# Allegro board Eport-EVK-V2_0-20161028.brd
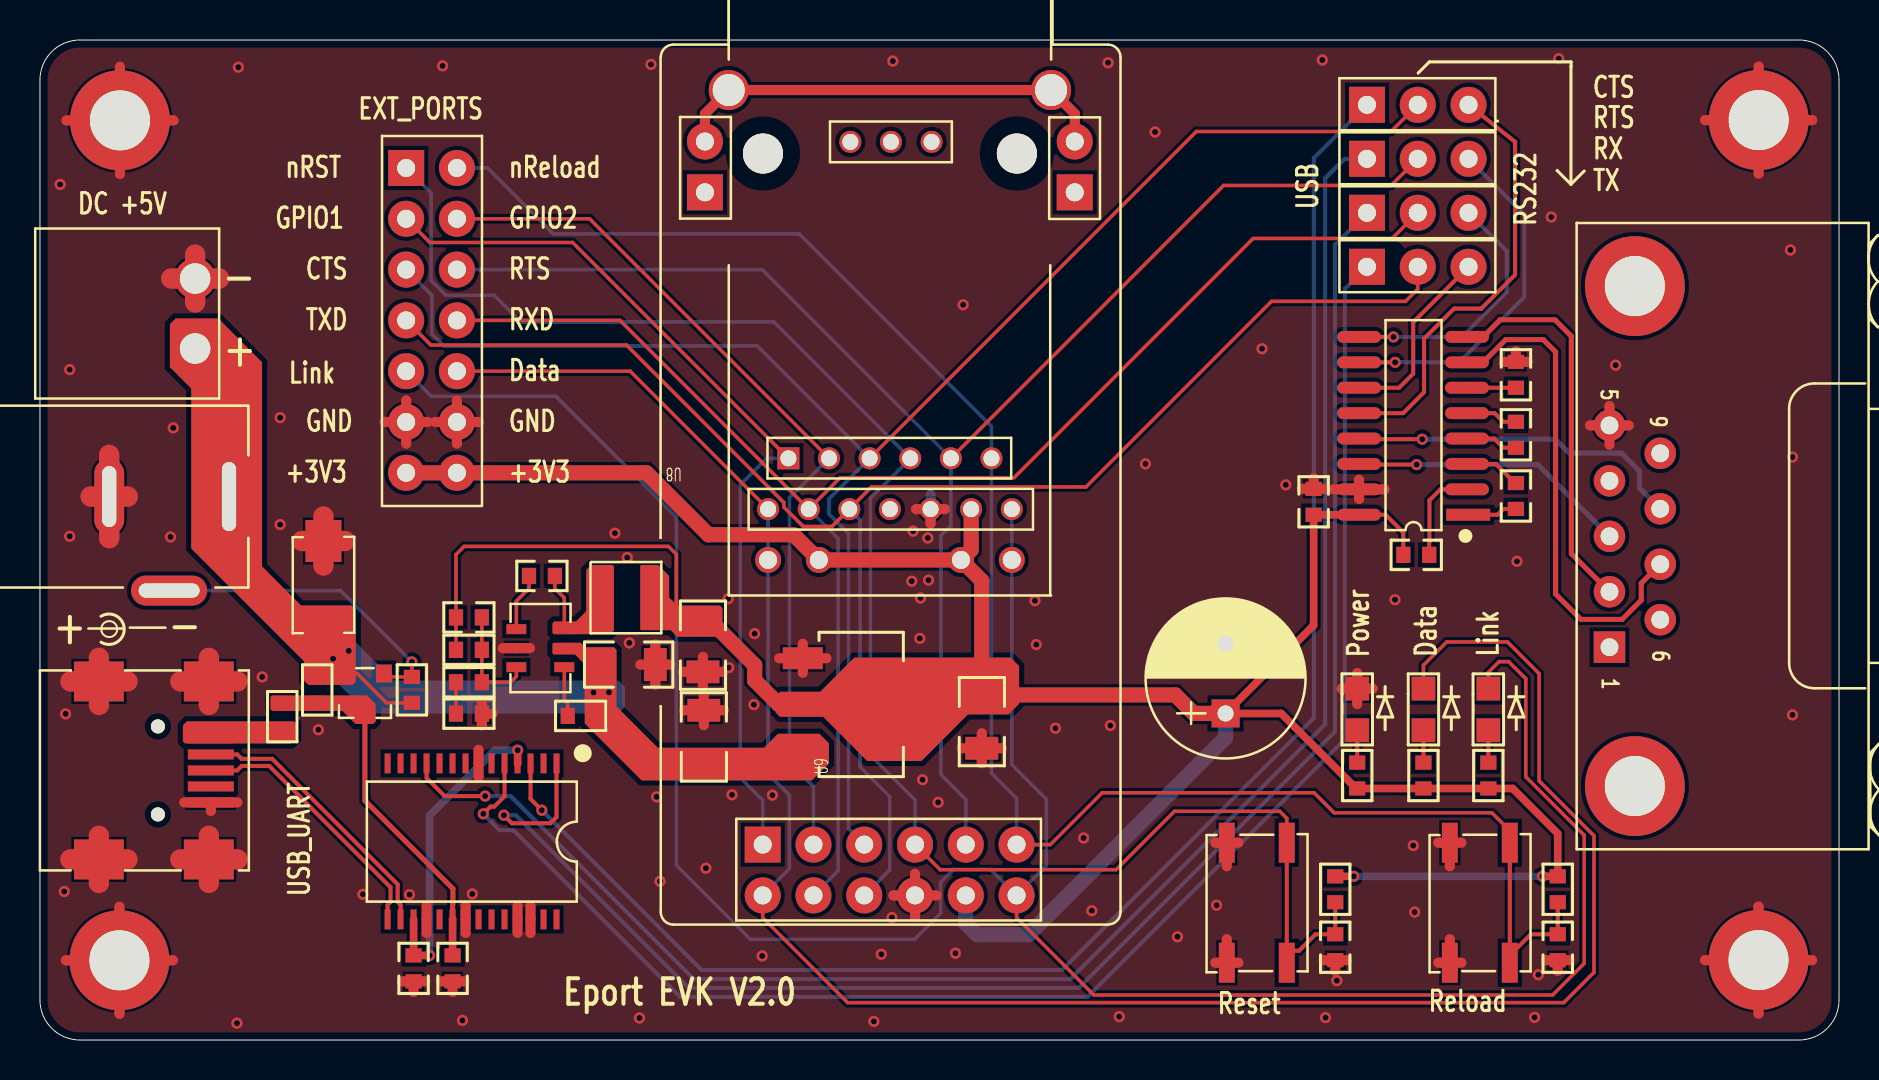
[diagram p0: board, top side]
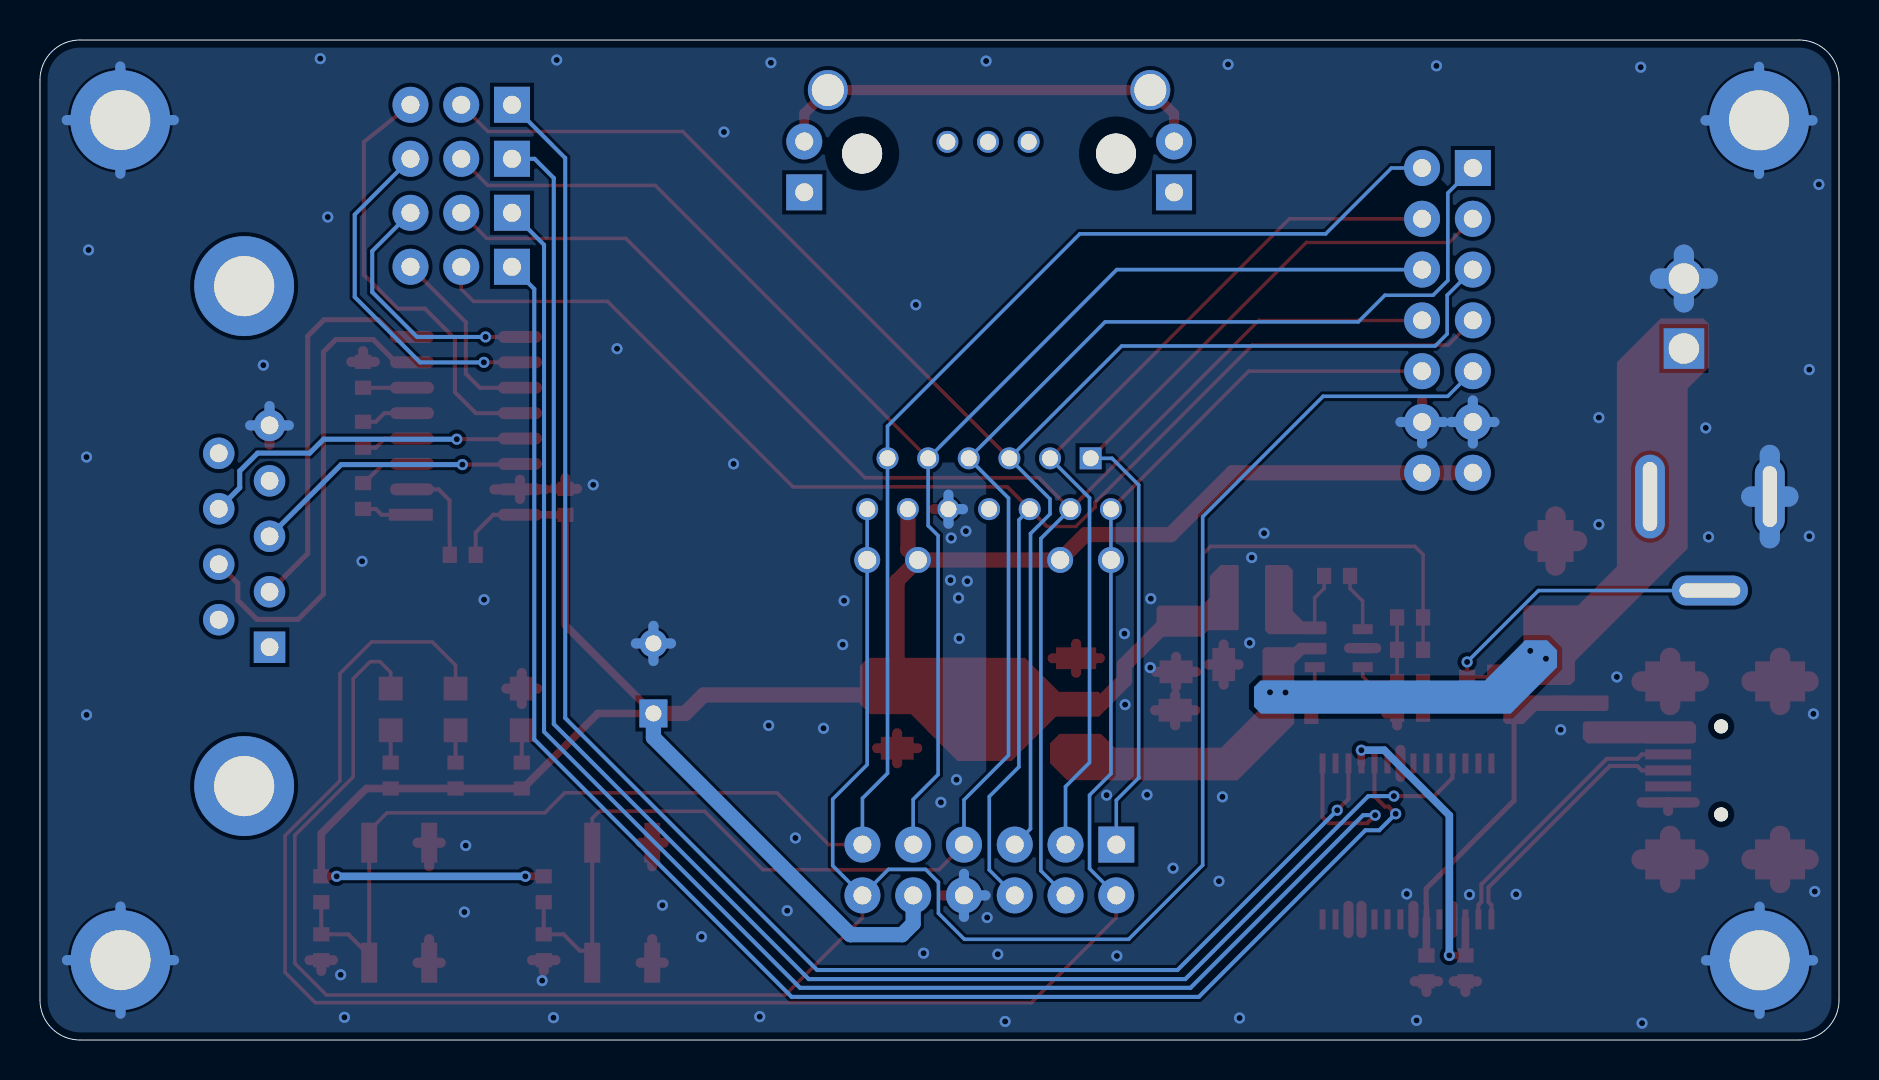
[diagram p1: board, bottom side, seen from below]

Outline 90 x 50 mm; copper layers: TOP, BOTTOM. Coordinates in mm from the lower left corner of the outline.
Outline path: 0,48 0,2 arc(0.59,0.59) 2,0 88,0 arc(89.41,0.59) 90,2 90,48 arc(89.41,49.41) 88,50 2,50 arc(0.59,49.41) 0,48

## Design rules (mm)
net group USB: nets N15375170 N15375190

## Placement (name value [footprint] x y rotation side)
C14  0.1uF  [C0603]  25.11 23.2 0 top
C15  10uF  [C1206]  29.45 18.77 180 top
C16  NI  [C0603]  21.46 21.13 180 top
C17  22uF  [C1206]  33.17 19.74 90 top
C18  0.1uF  [C0603]  73.84 27.2 270 top
C19  0.1uF  [C0603]  73.84 30.26 270 top
C20  0.1uF  [C0603]  63.71 26.91 270 top
C21  0.1uF  [C0603]  68.85 24.26 180 top
C22  0.1uF  [C0603]  73.84 33.26 270 top
C24  10uF  [C1206]  33.21 15.15 270 top
C25  10uF  [C1206]  47.11 15.92 90 top
C27  NI  [C0603]  75.93 4.64 90 top
C28  220uF  [RAD3-5]  59.31 18.08 90 top
C29  NI  [C0603]  64.8 4.64 90 top
C30  0.1uF  [C0603]  18.69 3.58 90 top
C31  0.1uF  [C0603]  20.64 3.58 90 top
D2  APT1608EC  [LED0603]  65.9 16.53 90 top
D3  APT1608SGC  [LED0603]  69.21 16.53 90 top
D4  APT1608SGC  [LED0603]  72.45 16.53 90 top
D7  SMAJ20CA  [DO-214AC]  14.18 22.75 270 top
F1  FUSE1  [R0603]  12.12 16.17 90 top
FIX1  -  [FIX-HOLE]  4 45.98 0 top
FIX2  -  [FIX-HOLE]  3.98 3.98 0 top
FIX3  -  [FIX-HOLE]  85.97 3.99 0 top
FIX4  -  [FIX-HOLE]  85.98 46 0 top
J1  -  [CP-002B]  6.46 27.17 270 top
J2  DB9  [DB-9]  79.78 37.69 270 top
J5  EDSTLZ1550/2  [THERM2]  7.76 34.57 90 top
J6  EXT ports  [DIP14]  18.32 43.6 270 top
J10  USB-MINI-B  [USB_MINI_B]  2.95 17.93 90 top
J11  UART Selection  [SIP3]  66.38 41.36 0 top
J12  nReady selection  [SIP3]  66.38 44.06 0 top
J13  nReady selection  [SIP3]  66.38 38.66 0 top
J14  nReady selection  [SIP3]  66.38 46.76 0 top
J15  nReady selection  [SIP_3]  40.54 44.91 0 top
L1  6.8uH  [L3012]  29.33 22.12 0 top
Q1  MOSFET_P  [SOT-23]  16.25 17.33 180 top
R4  100K 1%  [R0603]  21.46 19.51 180 top
R5  22K 1%  [R0603]  21.46 17.89 180 top
R6  100R 1%  [R0603]  21.46 16.32 180 top
R7  10K  [R0603]  27.05 16.2 0 top
R10  510R  [R0603]  65.9 13.22 90 top
R11  0R  [R0603]  69.21 13.22 90 top
R12  0R  [R0603]  72.45 13.22 90 top
R15  4.7K  [R0603]  75.93 7.54 270 top
R18  4.7K  [R0603]  64.8 7.54 270 top
R19  10K  [R0603]  18.61 17.51 270 top
R20  OR NC  [R0603]  13.87 17.5 270 top
S1  SWITCH  [SW-4]  72.03 6.86 180 top
S2  SWITCH  [SW-4]  60.87 6.86 180 top
U4  AP2114H  [SOT223]  41.11 16.79 270 top
U5  MAX3232  [SOIC-G16]  68.85 30.71 90 top
U6  SY8120  [SOT23-6]  23.83 20.54 270 top
U7  FT232RL  [SSOP-28]  25.84 13.83 180 top
U8  Eport 10  [EPORT]  37.44 29.08 180 top
U9  Eport 20  [EP20]  36.15 9.77 90 top

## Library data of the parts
C14-C22 C24 C25 C27 C29-C31 = C0603: Tolerance: *; User Part Number: *
C28 = CAP_POL_0
D2-D4 = LED: Tolerance: *; User Part Number: *
D7 = SMAJ20A
F1 = FUSE1: Tolerance: *; User Part Number: *
FIX1-FIX4 = FIX
J1 = CP-002B: User Part Number: Part No
J2 = RS232_0
J5 = SIP2
J6 = ?_0
J10 = USB-MINI-B_0
J11-J15 = HDR5X1_0
L1 = INDUCTOR
Q1 = MOSFET_P_0
R4-R7 R10-R12 R15 R18-R20 = R / 10 / K / 0402: Tolerance: *; User Part Number: *
S1 S2 = SWITCH_2
U4 = TLV1117-33: Tolerance: *; User Part Number: *
U5 = MAX3232_0
U6 = SY8120
U7 = FT232RL
U8 = Eport_4
U9 = Eport_5

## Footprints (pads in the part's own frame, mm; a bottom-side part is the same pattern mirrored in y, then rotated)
C0603
  rect 0.711x0.813 smd: 1(-0.648,0) 2(0.648,0)
C1206
  rect 1.143x1.651 smd: 1(-1.333,0) 2(1.333,0)
CP-002B
  oval 4.191x1.499 hole 3.454x0.711: 1(0,2.997)
  oval 3.81x1.499 hole 3.048x0.711: 2(0,-2.997)
  oval 1.499x3.81 hole 0.711x3.048: 3(4.699,0)
DB-9
  rect 1.575x1.575 hole 0.889: 1(18.055,-1.27)
  round 1.575 hole 0.889: 2(15.282,-1.27) 3(12.509,-1.27) 4(9.737,-1.27) 5(6.964,-1.27) 6(16.679,1.27) 7(13.906,1.27) 8(11.134,1.27) 9(8.361,1.27)
  round 4.995 hole 3.006: 10(0,0) 11(24.998,0)
DIP14
  rect 1.8x1.8 hole 0.9: 1(0,0)
  round 1.8 hole 0.9: 2(0,2.54) 3(2.54,0) 4(2.54,2.54) 5(5.08,0) 6(5.08,2.54) 7(7.62,0) 8(7.62,2.54) 9(10.16,0) 10(10.16,2.54) 11(12.7,0) 12(12.7,2.54) 13(15.24,0) 14(15.24,2.54)
DO-214AC
  rect 2.1x1.8 smd: 1(-2.2,0) 2(2.2,0)
EP20
  rect 1.8x1.8 hole 0.9: (32.614,2.89) (32.614,-15.61) 1(0,0)
  round 1.8 hole 0.9: 2(0,-2.54) 3(0,-5.08) 4(0,-7.62) 5(0,-10.16) 6(0,-12.7) 7(-2.54,0) 8(-2.54,-2.54) 9(-2.54,-5.08) 10(-2.54,-7.62) 11(-2.54,-10.16) 12(-2.54,-12.7) 13(35.154,2.89) 14(35.154,-15.61)
EPORT
  round 2 hole 3.3 unplated: (-11.43,-15.24) (1.27,-15.24)
  round 1.1 hole 0.8: (-5.08,2.54) 2(-2.032,0) 3(-4.064,0) 4(-6.096,0) 5(-8.128,0) 6(-10.16,0) 7(1.016,2.54) 8(-1.016,2.54) 9(-3.048,2.54) 10(-7.112,2.54) 11(-9.144,2.54) 12(-11.176,2.54)
  rect 1.1x1.1 hole 0.8: 1(0,0)
  round 1.3 hole 0.9: 13(1.016,5.08) 14(-1.524,5.08) 15(-8.636,5.08) 16(-11.176,5.08)
  round 2 hole 1.6: 19(2.985,-18.415) 20(-13.145,-18.415)
FIX-HOLE
  round 5 hole 3: 1(0,0)
L3012
  rect 0.8x3.2 smd: 1(-1.15,0) 2(1.15,0)
LED0603
  rect 1.194x1.194 smd: 1(-1.041,0) 2(1.041,0)
R0603
  rect 0.711x0.813 smd: 1(-0.648,0) 2(0.648,0)
RAD3-5
  rect 1.4x1.4 hole 0.8: 1(-1.75,0)
  round 1.4 hole 0.8: 2(1.75,0)
SIP3
  rect 1.8x1.8 hole 0.9: 1(0,0)
  round 1.8 hole 0.9: 2(2.54,0) 3(5.08,0)
SIP_3
  round 1.1 hole 0.8: 1(0,0) 2(2.032,0) 3(4.064,0)
SOIC-G16
  rect 0.6x2.2 smd: 1(-4.445,-2.6)
  oval 0.6x2.2 smd: 2(-3.175,-2.54) 3(-1.905,-2.54) 4(-0.635,-2.54) 5(0.635,-2.54) 6(1.905,-2.54) 7(3.175,-2.54) 8(4.445,-2.54) 9(4.445,2.86) 10(3.175,2.86) 11(1.905,2.86) 12(0.635,2.86) 13(-0.635,2.86) 14(-1.905,2.86) 15(-3.175,2.86) 16(-4.445,2.86)
SOT23-6
  rect 0.5x1 smd: 1(0,0) 2(0.95,0) 3(1.9,0) 4(1.9,2.4) 5(0.95,2.4) 6(0,2.4)
SOT223
  rect 1.092x2.007 smd: 1(-2.3,-2.95) 2(0,-2.95) 3(2.3,-2.95)
  rect 3.302x2.007 smd: 4(0,2.95)
SOT-23
  rect 0.8x0.9 smd: 1(-0.95,-1) 2(0.95,-1) 3(0,1)
SSOP-28
  rect 0.3x1 smd: 1(0,0) 2(0.65,0) 3(1.3,0) 4(1.95,0) 5(2.6,0) 6(3.25,0) 7(3.9,0) 8(4.55,0) 9(5.2,0) 10(5.85,0) 11(6.5,0) 12(7.15,0) 13(7.8,0) 14(8.45,0) 15(8.45,7.8) 16(7.8,7.8) 17(7.15,7.8) 18(6.5,7.8) 19(5.85,7.8) 20(5.2,7.8) 21(4.55,7.8) 22(3.9,7.8) 23(3.25,7.8) 24(2.6,7.8) 25(1.95,7.8) 26(1.3,7.8) 27(0.65,7.8) 28(0,7.8)
SW-4
  rect 0.8x2 smd: 1(-1.5,-3) 2(-1.5,3) 3(1.5,-3) 4(1.5,3)
THERM2
  rect 2.032x2.032 hole 1.524: 1(0,0)
  round 2.032 hole 1.524: 2(3.5,0)
USB_MINI_B
  round 0.7 hole 0.9 unplated: (-6.65,-2.95) (-2.25,-2.95)
  rect 0.5x2.3 smd: 1(-2.85,-5.6) 2(-3.65,-5.6) 3(-4.45,-5.6) 4(-5.25,-5.6) 5(-6.05,-5.6)
  rect 2x2.5 smd: 6(0,0) 7(-8.9,0) 8(0,-5.5) 9(-8.9,-5.5)

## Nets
+3V3: C16.2 C17.2 C20.2 C21.2 C25.2 C28.1 J6.13 J6.14 L1.2 R4.2 R10.1 R11.1 R12.1 R15.1 R18.1 U4.2(VOUT1) U4.4(VOUT2) U5.16(VCC) U8.11(3V3) U8.14(LED_3V3#14) U8.15(LED_3V3#15) U9.11(3V3)
GND_POWER: C15.1 C17.1 C20.1 C22.1 C24.1 C25.1 C27.1 C28.2 C29.1 C30.1 C31.1 D2.2 D7.1 FIX1.1 FIX2.1 FIX3.1 FIX4.1 J1.2 J2.5 J5.2 J6.11 J6.12 J10.5 J10.6 J10.7 J10.8 J10.9 R6.1 S1.3 S1.4 S2.3 S2.4 U4.1(GND) U5.15(GND) U6.2(GND) U7.7(GND1) U7.18(GND2) U7.21(GND3) U7.25(AGND) U7.26(TEST) U8.10(GND) U9.10(GND)
VIN: C15.2 C24.2 D7.2 J1.1 J5.1 Q1.2(S) R7.2 R19.2 R20.1 U4.3(VIN) U6.5(IN)
232_CTS: J14.3 U5.12(R1OUT)
232_RTS: J12.3 U5.10(T2IN)
232_RX: J11.3 U5.9(R2OUT)
232_TX: J13.3 U5.11(T1IN)
E_GND: U8.19(E_GND#19) U8.20(E_GND#20) U9.13(E_GND#13) U9.14(E_GND#14)
LED1: D3.2 J6.10 U8.7(LED_1) U8.13(LED2) U9.7(LED_1)
LED2: D4.2 J6.9 U8.12(LED_2) U8.16(LED1) U9.12(LED_2)
RELOAD: C27.2 J6.2 R15.2 S1.1 S1.2 U8.6(RELOAD) U9.6(RELOAD)
RS232_CTS: J2.8 U5.13(R1IN)
RS232_RTS: J2.7 U5.7(T2OUT)
RS232_RX: J2.2 U5.8(R2IN)
RS232_TX: J2.3 U5.14(T1OUT)
SW: J1.3 Q1.1(G) R19.1
SYS_RST: C29.2 J6.1 R18.2 S2.1 S2.2 U8.4(SYS_RST) U9.4(SYS_RST)
UART0_CTS: J6.5 J14.2 U8.3(UART0_CTS) U9.3(UART0_CTS)
UART0_RTS: J6.6 J12.2 U8.5(UART0_RTS) U9.5(UART0_RTS)
UART0_RX: J6.8 J11.2 U8.8(UART0_RX) U9.8(UART0_RX)
UART0_TX: J6.7 J13.2 U8.9(UART0_TX) U9.9(UART0_TX)
UART1_RX: J6.4 U8.2(UART1_RX) U9.2(UART1_RX)
UART1_TX: J6.3 U8.1(UART1_TX) U9.1(UART1_TX)
USB_CTS: J12.1 U7.11(CTS#)
USB_IN: C31.2 F1.2 Q1.3(D) R20.2 U7.20(VCC)
USB_RTS: J14.1 U7.3(RTS#)
USB_RX: J13.1 U7.5(RXD)
USB_TX: J11.1 U7.1(TXD)
N00175: C14.1 U6.1(BS)
N00182: C14.2 L1.1 U6.6(LX)
N00203: C16.1 R4.1 R5.1 U6.3(FB)
N00338: R7.1 U6.4(EN)
N01191: C19.1 U5.5(C2-)
N01195: C19.2 U5.4(C2+)
N01202: C18.2 U5.1(C1+)
N01209: C18.1 U5.3(C1-)
N01519: C21.1 U5.2(VDD)
N01837: C22.2 U5.6(VEE)
N15326682: D2.1 R10.2
N15326750: D3.1 R11.2
N15326833: D4.1 R12.2
N15332885: R5.2 R6.2
N15375121: F1.1 J10.1
N15375170: J10.2 U7.16(USBDM)
N15375190: J10.3 U7.15(USBDP)
N15376984: C30.2 U7.4(VCCIO) U7.17(3V3OUT)

Pads without a net: J2 1 4 6 9 10 11; J10 4; J15 1 2 3; U7 2 6 8 9 10 12 13 14 19 22 23 24 27 28

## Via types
v1: diameter 0.559, hole 0.305, TOP to BOTTOM, 93 vias

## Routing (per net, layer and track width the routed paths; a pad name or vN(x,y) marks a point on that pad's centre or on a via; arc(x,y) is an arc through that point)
+3V3: length 157.4
  TOP w0.178: R4.2 C16.2 20.81,24.27 21.22,24.68 31.44,24.68 31.84,24.28 31.84,21.44
  TOP w0.203: U5.16 67.32,26.26 68.2,25.38 C21.2
  TOP w0.381: v1(75.16,8.18) R15.1 75.93,10.32 73.67,12.58 R12.1 R11.1 R10.1 65.84,12.58 62.09,16.33 C28.1 63.71,20.73 C20.2 U5.16 ; v1(65.72,8.18) R18.1
  TOP w0.762: J6.13 J6.14 30.34,28.36 33.44,25.26 37.7,25.26 U8.14 U8.15 ; C25.2 56.79,17.25 57.72,16.33 C28.1 ; C25.2 47.11,22.96 U8.15 ; C25.2 46.65,16.79 U4.4 U4.2 36.94,16.79 35.75,17.98 35.75,18.74 33.42,21.07 C17.2 ; U8.15 46.58,24.51 U8.11
  BOTTOM w0.381: v1(75.16,8.18) v1(65.72,8.18)
  BOTTOM w0.762: U9.11 46.31,5.82 46.87,5.27 49.46,5.27 59.31,15.12 C28.1
GND_POWER: length 231.5
  TOP w0.508: 21.94,13.15 U7.7 21.94,14.51 ; 32.21,16.49 C24.1 ; C24.1 34.21,16.49 ; C24.1 33.21,17.24 ; C24.1 33.21,15.74 ; C17.1 34.17,18.41 ; C17.1 32.16,18.41 ; C17.1 33.17,19.16 ; C17.1 33.17,17.66 ; 70.53,8.69 S1.3 ; S1.3 69.95,9.86 ; S1.3 71.11,9.86 ; FIX1.1 6.68,45.98 ; FIX1.1 4,43.3 ; FIX1.1 1.32,45.98 ; FIX1.1 4,48.66 ; 46.11,14.59 C25.1 ; C25.1 47.11,15.34 ; C25.1 48.12,14.59 ; C25.1 47.11,13.84 ; C20.1 64.3,27.56 ; C20.1 63.13,27.56 ; C20.1 63.71,28.09 ; FIX4.1 85.98,48.67 ; FIX4.1 88.66,46 ; FIX4.1 83.3,46 ; FIX4.1 85.98,43.32 ; 17.24,30.9 J6.11 ; J6.11 19.4,30.9 ; J6.11 18.32,29.82 ; J6.11 18.32,31.98 ; C22.1 73.84,34.44 ; C22.1 74.42,33.91 ; C22.1 73.25,33.91 ; 22.11,15.73 R6.1 ; R6.1 22.11,16.9 ; R6.1 22.64,16.32 ; C15.1 30.78,19.77 ; C15.1 31.53,18.77 ; C15.1 30.03,18.77 ; C15.1 30.78,17.77 ; 20.64,2.4 C31.1 ; C31.1 21.22,2.93 ; C31.1 20.06,2.93 ; C28.2 59.31,20.71 ; C28.2 60.19,19.83 ; C28.2 59.31,18.95 ; C28.2 58.43,19.83 ; D2.2 65.9,18.35 ; D2.2 65.12,17.57 ; D2.2 65.9,16.8 ; D2.2 66.67,17.57 ; 36.98,19.09 U4.1 ; U4.1 38.16,18.36 ; U4.1 38.16,19.81 ; U4.1 39.34,19.09 ; S1.4 70.53,5.04 ; S1.4 69.95,3.86 ; S1.4 71.11,3.86 ; U5.15 67.26,27.53 ; U5.15 65.99,27.06 ; U5.15 65.99,28.01 ; U5.15 64.71,27.53 ; FIX2.1 6.65,3.98 ; FIX2.1 3.98,1.31 ; FIX2.1 1.3,3.98 ; FIX2.1 3.98,6.66 ; U9.10 43.77,8.31 ; U9.10 44.85,7.23 ; U9.10 43.77,6.15 ; U9.10 42.7,7.23 ; 78.51,29.77 J2.5 ; J2.5 77.55,30.73 ; J2.5 79.48,30.73 ; J2.5 78.51,31.7 ; 23.15,19.59 U6.2 24.51,19.59 ; 64.21,3.99 C29.1 ; C29.1 64.8,3.46 ; C29.1 65.38,3.99 ; S2.4 59.95,3.86 ; S2.4 58.79,3.86 ; S2.4 59.37,5.04 ; J6.12 20.86,31.98 ; J6.12 19.78,30.9 ; J6.12 21.94,30.9 ; J6.12 20.86,29.82 ; 7.22,11.88 J10.5 ; J10.5 9.88,11.88 ; J10.5 8.55,11.45 ; FIX3.1 88.65,3.99 ; FIX3.1 83.29,3.99 ; FIX3.1 85.97,1.32 ; FIX3.1 85.97,6.67 ; 75.34,3.99 C27.1 ; C27.1 76.51,3.99 ; C27.1 75.93,3.46 ; 18.69,2.4 C30.1 ; C30.1 18.11,2.93 ; C30.1 19.27,2.93 ; 19.34,6.71 U7.18 19.34,5.35 ; 21.29,5.35 U7.21 21.29,6.71 ; U8.10 45.28,26.54 ; U8.10 44.55,25.82 ; U8.10 43.82,26.54 ; 24.54,5.35 U7.26 24.54,6.71 ; 23.89,5.35 U7.25 23.89,6.71 ; 59.37,8.69 S2.3 ; S2.3 58.79,9.86 ; S2.3 59.95,9.86
  TOP w1.016: J5.2 7.76,36.88 ; J5.2 6.57,38.07 ; J5.2 8.95,38.07 ; J5.2 7.76,39.27 ; J10.7 4.38,9.03 ; J10.7 2.95,10.21 ; J10.7 1.52,9.03 ; J10.7 2.95,7.85 ; D7.1 14.18,23.72 ; D7.1 13.1,24.95 ; D7.1 15.26,24.95 ; D7.1 14.18,26.18 ; J10.6 2.95,19.11 ; J10.6 1.52,17.93 ; J10.6 2.95,16.75 ; J10.6 4.38,17.93 ; J10.9 8.45,7.85 ; J10.9 7.02,9.03 ; J10.9 9.88,9.03 ; J10.9 8.45,10.21 ; J10.8 8.45,16.75 ; J10.8 7.02,17.93 ; J10.8 9.88,17.93 ; J10.8 8.45,19.11 ; J1.2 2.54,27.17 ; J1.2 3.46,25.09 ; J1.2 3.46,29.25 ; J1.2 4.39,27.17
  BOTTOM w0.508: 85.97,1.32 FIX3.1 ; FIX3.1 88.65,3.99 ; FIX3.1 83.29,3.99 ; FIX3.1 85.97,6.67 ; 85.98,43.32 FIX4.1 ; FIX4.1 85.98,48.67 ; FIX4.1 88.66,46 ; FIX4.1 83.3,46 ; 18.32,29.82 J6.11 ; J6.11 18.32,31.98 ; J6.11 19.4,30.9 ; J6.11 17.24,30.9 ; 43.82,26.54 U8.10 ; U8.10 44.55,27.27 ; U8.10 44.55,25.82 ; 43.77,6.15 U9.10 ; U9.10 42.7,7.23 ; U9.10 43.77,8.31 ; 58.43,19.83 C28.2 ; C28.2 60.19,19.83 ; C28.2 59.31,18.95 ; C28.2 59.31,20.71 ; 77.55,30.73 J2.5 ; J2.5 79.48,30.73 ; J2.5 78.51,31.7 ; FIX1.1 6.68,45.98 ; FIX1.1 4,43.3 ; FIX1.1 4,48.66 ; FIX1.1 1.32,45.98 ; FIX2.1 3.98,6.66 ; FIX2.1 6.65,3.98 ; FIX2.1 3.98,1.31 ; FIX2.1 1.3,3.98 ; 19.78,30.9 J6.12 ; J6.12 20.86,29.82 ; J6.12 21.94,30.9
  BOTTOM w1.016: J1.2 3.46,29.25 ; J1.2 3.46,25.09 ; J1.2 4.39,27.17 ; J1.2 2.54,27.17 ; J5.2 7.76,39.27 ; J5.2 8.95,38.07 ; J5.2 6.57,38.07 ; J5.2 7.76,36.88
  vias: v1(1.01,42.78) v1(1.21,7.43) v1(1.28,16.31) v1(1.49,33.52) v1(1.49,25.19) v1(6.53,25.15) v1(6.66,30.6) v1(9.92,48.64) v1(9.85,0.84) v1(11.12,18.15) v1(12.01,31.12) v1(12.01,25.77) v1(13.93,15.51) v1(16.16,7.28) v1(18.49,7.27) v1(20.14,48.71) v1(21.13,0.98) v1(21.62,7.3) v1(28.76,25.34) v1(29.38,24.12) v1(29.48,19.85) v1(29.99,1.1) v1(30.56,48.78) v1(30.85,12.16) v1(31.02,7.94) v1(33.31,8.59) v1(34.43,22.07) v1(34.45,18.62) v1(34.62,12.26) v1(35.75,20.32) v1(35.71,16.77) v1(36.13,4.2) v1(36.64,12.24) v1(41.72,0.93) v1(42.08,4.29) v1(42.62,6.12) v1(42.67,48.95) v1(43.61,22.94) v1(43.68,25.44) v1(44.05,22.1) v1(44.01,20.08) v1(44.15,13.01) v1(44.42,25.1) v1(44.45,22.99) v1(44.93,11.88) v1(45.8,4.34) v1(46.18,36.76) v1(49.77,21.96) v1(49.84,19.77) v1(50.8,15.59) v1(52.21,10.1) v1(52.62,6.47) v1(53.43,48.86) v1(53.54,15.72) v1(53.99,1.17) v1(55.3,28.8) v1(55.78,45.4) v1(56.9,5.16) v1(58.86,6.74) v1(61.13,34.56) v1(62.32,27.76) v1(64.15,49) v1(64.31,1.12) v1(64.88,2.97) v1(67.78,22.02) v1(68.7,9.72) v1(68.77,6.4) v1(73.89,23.94) v1(74.77,1.13) v1(74.96,3.26) v1(75.6,41.15) v1(75.98,49.07) v1(78.82,33.74) v1(87.57,39.5) v1(87.67,29.15) v1(87.67,16.26)
VIN: length 11.2
  TOP w0.178: Q1.2 15.87,18.33 17.34,16.86 R19.2 ; v1(15.45,19.46) 14.58,20.15 D7.2 15.3,20.55 15.45,20.4 v1(14.66,19.07) ; C15.2 28.12,17.73 v1(27.69,17.38) R7.2
  vias: v1(28.46,17.39)
232_CTS: length 21.9
  TOP w0.203: J14.3 73.79,44.9 73.79,38.26 72.1,36.57 70.74,36.57 69.24,35.07 69.24,32.39 68.19,31.34 U5.12
232_RTS: length 17.7
  TOP w0.203: U5.10 v1(67.79,33.88)
  BOTTOM w0.203: v1(67.79,33.88) 70.98,33.88 74.25,37.15 74.25,41.27 J12.3
232_RX: length 13.1
  TOP w0.203: U5.9 v1(67.71,35.15)
  BOTTOM w0.203: v1(67.71,35.15) 71.14,35.15 73.38,37.4 73.38,39.45 J11.3
232_TX: length 9.5
  TOP w0.203: U5.11 67.99,32.61 68.69,33.31 68.69,35.89 J13.3
E_GND: length 22.3
  TOP w0.508: U9.13 33.26,46.31 U8.19 U8.20 51.76,46.32 U9.14
LED1: length 108
  TOP w0.178: J6.10 29.53,33.44 U8.7 ; U9.7 36.15,6.11 40.4,1.87 76.22,1.87 77.74,3.38 77.74,10.21 74.99,12.96 74.99,18.32 73.41,19.9 70.37,19.9 69.21,18.74 D3.2
  BOTTOM w0.178: U8.7 U8.13 36.42,13.31 37.49,12.24 37.49,8.57 U9.7
LED2: length 126.5
  TOP w0.178: U9.12 48.85,6.11 52.72,2.25 75.67,2.25 77.25,3.83 77.25,10.24 74.33,13.16 74.33,18.06 73.47,18.92 72.99,18.92 72.45,18.38 D4.2
  BOTTOM w0.178: U8.12 U8.16 48.61,13.77 50.34,12.04 50.34,8.72 U9.12 47.55,8.53 45.7,8.53 45.05,7.89 45.05,6.34 43.75,5.03 35.54,5.03 31.83,8.74 31.83,26.16 25.81,32.19 19.57,32.19 J6.9
RELOAD: length 91.1
  TOP w0.178: U9.6 50.54,9.77 53.14,12.36 63.74,12.36 64.74,11.36 72.63,11.36 73.53,10.46 S1.1
  TOP w0.203: 73.53,4.24 74.58,5.29 C27.2 R15.2 ; 73.53,4.24 S1.1 ; 73.53,4.24 S1.2
  BOTTOM w0.178: U9.6 48.85,12.08 47.6,13.34 U8.6 47.6,30.69 37.98,40.31 25.68,40.31 22.39,43.6 J6.2
RS232_CTS: length 17
  TOP w0.203: U5.13 65.99,30.07 66.02,30.04 v1(69.15,30.04)
  BOTTOM w0.254: v1(69.15,30.04) 75.81,30.04 76.5,29.34 79.11,29.34 80.01,28.45 80.01,27.61 J2.8
RS232_RTS: length 24.7
  TOP w0.254: J2.7 80.1,22.84 80.1,21.99 79.14,21.03 77.09,21.03 75.82,22.3 75.82,34.4 75.2,35.02 73.32,35.02 72.19,33.88 U5.7
RS232_RX: length 19.5
  TOP w0.254: J2.2 76.61,24.32 76.61,35.19 75.78,36.01 73.05,36.01 72.19,35.15 U5.8
RS232_TX: length 14
  TOP w0.203: U5.14 65.99,28.8 66.02,28.77 v1(68.87,28.77)
  BOTTOM w0.254: v1(68.87,28.77) 74.93,28.77 J2.3
SW: length 15.8
  TOP w0.178: Q1.1 17.38,18.15 R19.1 v1(18.61,18.9)
  BOTTOM w0.178: v1(18.61,18.9) 15.03,22.47 J1.3
SYS_RST: length 86.9
  TOP w0.178: S2.1 62.37,11.08 62.02,11.43 56.75,11.43 53.83,8.52 45.03,8.52 U9.4
  TOP w0.203: 62.37,4.46 S2.1 ; 62.37,4.46 62.99,4.46 63.81,5.29 C29.2 R18.2 ; 62.37,4.46 S2.2
  BOTTOM w0.178: J6.1 19.57,42.35 19.57,37.98 20.31,37.24 22.71,37.24 24.05,35.9 36.71,35.9 U8.4 41.55,27.09 41.55,14.23 43.77,12 U9.4
UART0_CTS: length 83.9
  TOP w0.178: U8.3 57.85,45.43 67.59,45.43 J14.2
  BOTTOM w0.178: J6.5 19.6,37.24 19.6,35.3 20.2,34.7 35.88,34.7 U8.3 39.47,27.05 39.47,26.29 40.45,25.32 40.45,10.56 U9.3
UART0_RTS: length 78.2
  TOP w0.178: U8.5 59.21,42.73 67.59,42.73 J12.2
  BOTTOM w0.178: U9.5 46.31,12.03 45.07,13.28 45.07,25.22 45.57,25.72 U8.5 36.13,38.52 J6.6
UART0_RX: length 78.5
  TOP w0.178: J11.2 67.64,40.08 60.69,40.08 48.73,28.11 40.03,28.11 U8.8 29.02,35.98 J6.8
  BOTTOM w0.178: U9.8 39.93,8.46 39.93,25.07 U8.8
UART0_TX: length 81.7
  TOP w0.178: J6.7 19.55,34.75 29.34,34.75 37.21,26.87 37.21,26.64 38.18,25.68 39.62,25.68 U8.9 41.6,27.65 52.33,27.65 61.61,36.93 68.31,36.93 68.92,37.54 J13.2
  BOTTOM w0.178: U9.9 42.51,8.5 42.51,12.17 41.03,13.65 41.03,26 U8.9
UART1_RX: length 44.2
  TOP w0.178: J6.4 27.49,41.06 U8.2
  BOTTOM w0.178: U9.2 38.69,12.67 37.49,13.87 37.49,27.11 U8.2
UART1_TX: length 45.5
  TOP w0.178: J6.3 19.5,39.88 26.65,39.88 U8.1
  BOTTOM w0.178: U9.1 36.15,11.99 35.03,13.11 35.03,27.75 36.37,29.08 U8.1
USB_CTS: length 84.9
  TOP w0.203: v1(22.27,12.2) 20.25,12.2 19.34,13.1 U7.11
  BOTTOM w0.203: v1(22.27,12.2) 23.55,12.2 32.7,3.05 51.54,3.05 64.29,15.8 64.29,43.1 65.26,44.06 J12.1
USB_IN: length 13.9
  TOP w0.254: U7.20 20.64,6.78 20.66,6.8 20.66,7.57 16.25,11.97 Q1.3
  TOP w0.381: U7.20 C31.2
USB_RTS: length 81.5
  TOP w0.203: v1(25.1,11.49) 24.54,12.05 U7.3
  BOTTOM w0.203: J14.1 63.72,44.1 63.72,16.1 51.12,3.5 33.1,3.5 v1(25.1,11.49)
USB_RX: length 79.4
  TOP w0.203: U7.5 23.24,12.18 22.72,11.67 22.54,11.67 v1(22.18,11.31)
  BOTTOM w0.203: J13.1 65.27,37.55 65.27,15.03 52.4,2.16 32.02,2.16 23.69,10.49 23,10.49 v1(22.18,11.31)
USB_TX: length 82.7
  TOP w0.203: v1(23.21,11.24) 23.61,10.84 25.53,10.84 25.84,11.14 U7.1
  BOTTOM w0.203: J11.1 64.78,39.76 64.78,15.41 51.98,2.61 32.44,2.61 23.81,11.24 v1(23.21,11.24)
N00175: length 2.9
  TOP w0.178: U6.1 23.83,21.95 24.46,22.58 C14.1
N00182: length 2.9
  TOP w0.178: C14.2 25.76,22.58 26.23,22.11 U6.6
N00203: length 5.6
  TOP w0.178: U6.3 23.83,18.18 23.54,17.89 R5.1 R4.1 C16.1
N00338: length 2.5
  TOP w0.178: R7.1 26.4,16.83 26.23,17 U6.4
N01191: length 2.6
  TOP w0.203: U5.5 72.77,31.34 73.2,30.91 C19.1
N01195: length 2.6
  TOP w0.203: C19.2 73.2,29.61 72.74,30.07 U5.4
N01202: length 2.5
  TOP w0.203: C18.2 73.2,26.55 72.91,26.26 U5.1
N01209: length 2.8
  TOP w0.203: U5.3 72.83,28.8 73.78,27.85 C18.1
N01519: length 4.8
  TOP w0.203: U5.2 70.06,27.53 69.51,26.98 69.51,24.9 69.5,24.89 C21.1
N01837: length 2.4
  TOP w0.203: U5.6 C22.2
N15326682: length 1.6
  TOP w0.203: D2.1 R10.2
N15326750: length 1.6
  TOP w0.203: R11.2 D3.1
N15326833: length 1.6
  TOP w0.203: R12.2 D4.1
N15332885: length 1.6
  TOP w0.178: R5.2 R6.2
N15375170: length 13.8
  TOP w0.203: J10.2 9.87,14.28 10.09,14.06 11.62,14.06 17.89,7.78 17.89,6.9 18.04,6.76 U7.16
N15375190: length 13.3
  TOP w0.203: J10.3 9.87,13.48 10.09,13.7 11.47,13.7 17.54,7.63 17.54,6.9 17.39,6.76 U7.15
N15376984: length 16
  TOP w0.381: v1(23.9,14.49) 23.9,13.84 U7.4 ; v1(19.49,4.23) C30.2 U7.17
  BOTTOM w0.381: v1(23.9,14.49) 22.75,14.49 19.49,11.23 v1(19.49,4.23)

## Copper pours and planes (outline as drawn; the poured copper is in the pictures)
+3V3 on TOP (solid shape): 31.47,23.2 31.47,22.12 31.88,21.72 34.01,21.72 34.14,21.59 34.14,20.42 33.88,20.16 31.88,20.16 31.55,20.49 30.07,20.49 30.03,20.53 30.03,23.7 30.08,23.75 30.93,23.75
+3V3 on TOP (solid shape): 48.98,18.7 48.98,16.8 48.46,16.28 46.43,16.28 44.09,13.95 41.39,13.95 39.17,16.16 37.01,16.16 36.81,16.37 36.81,17.18 37.04,17.41 39.03,17.41 40.73,19.12 48.56,19.12
GND_POWER on TOP: 88,49.62 89.14,49.14 89.62,48 89.62,2 89.14,0.86 88,0.38 2,0.38 0.86,0.86 0.38,2 0.38,48 0.86,49.14 2,49.62 ; 10 cut-outs
GND_POWER on BOTTOM: 88,49.62 89.14,49.14 89.62,48 89.62,2 89.14,0.86 88,0.38 2,0.38 0.86,0.86 0.38,2 0.38,48 0.86,49.14 2,49.62 ; 15 cut-outs
VIN on TOP (solid shape): 11.11,33.89 11.11,23.68 13.06,21.73 15.59,21.73 15.8,21.51 15.8,17.92 15.64,17.75 13.43,17.75 13.21,17.97 13.21,18.93 7.57,24.58 7.57,32.58 6.5,33.65 6.5,35.79 6.79,36.08 8.92,36.08
VIN on TOP (solid shape): 27.27,19.64 28.71,19.64 28.84,19.51 28.84,16.68 30.9,14.62 36.22,14.62 36.92,15.31 38.99,15.31 39.47,14.83 39.47,13.83 38.62,12.98 30.09,12.98 27.25,15.82 27.25,18.79 26.76,19.28 25.69,19.28 25.64,19.33 25.64,19.81 25.69,19.86 27.05,19.86
VIN on BOTTOM (solid shape): 17.71,17.98 28.94,17.98 29.27,17.65 29.27,16.67 28.92,16.32 16.43,16.32 14.11,18.64 14.11,19.49 14.61,19.99 15.7,19.99
USB_IN on TOP (solid shape): 16.8,16.79 16.8,15.93 16.67,15.8 15.78,15.8 15.13,16.45 11.62,16.45 11.53,16.54 11.53,17.15 11.6,17.23 16.36,17.23
N00182 on TOP (solid shape): 28.71,23.68 28.71,20.48 28.52,20.29 25.7,20.29 25.64,20.35 25.64,20.84 25.72,20.93 26.81,20.93 27.33,21.44 27.33,23.5 27.57,23.75 28.64,23.75
N15375121 on TOP (solid shape): 12.82,15.82 12.82,15.06 12.58,14.83 7.25,14.83 7.15,14.93 7.15,15.73 7.35,15.93 12.7,15.93

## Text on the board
Ref Des/Assembly Top: J17 | J16 | J20 | J18 | J19
Ref Des/Silkscreen Top: DC +5V | GPIO1 | nRST | +3V3 | Link | CTS | TXD | GND | EXT_PORTS | nReload | GPIO2 | RTS | RXD | Data | Reset | Reload | RX | TX | USB_UART | USB | Power | RS232 | Eport EVK V2.0
User.5: FIGURE | SIZE | 12.0 | 31.496 | 35.0 | 35.433 | 60.0 | 62.992 | 118.11 | 118.331 | 129.921 | 120.0x28.0 | 136.0x28.0 | DRILL CHART: TOP to BOTTOM | ALL UNITS ARE IN MILS | TOLERANCE | +2.0/-2.0 | +0.0/-0.0 | +5.0/-5.0 | PLATED | NON-PLATED | QTY | 93 | 1 | 15 | 2 | 9 | 4 | 42
